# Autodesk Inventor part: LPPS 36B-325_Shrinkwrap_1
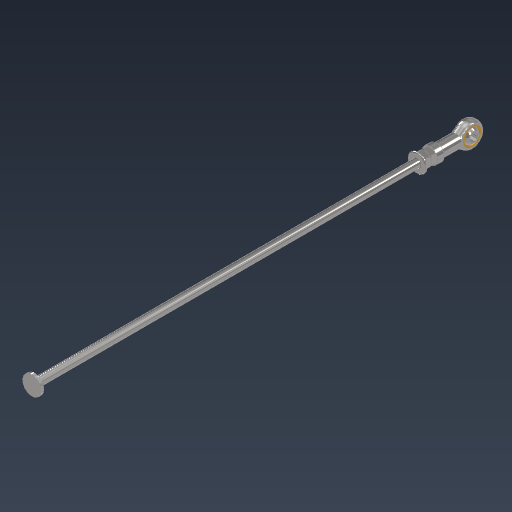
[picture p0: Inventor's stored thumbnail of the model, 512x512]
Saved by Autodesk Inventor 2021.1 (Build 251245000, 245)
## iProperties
Created: 2020-09
Part Number: LPPS 36B-325_Shrinkwrap_1
Material: Generic
Document SubType Name: Modeling
Designer: J. Nielson
Density: 1 g/cm^3
Appearance: Default
Author: J. Nielson
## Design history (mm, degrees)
derived "LPPS 36B-325.iam"
body "Solid1"
node "LPPS-36B-325 ROD.ipt:1"
node "Custom Flanged Nut.ipt:1"
body "Solid2"
node "FEMALE Rod End SW.ipt:1"
body "Solid3"
node "JIS B 1181 - M8x1(4).ipt:1"
body "Solid4"
